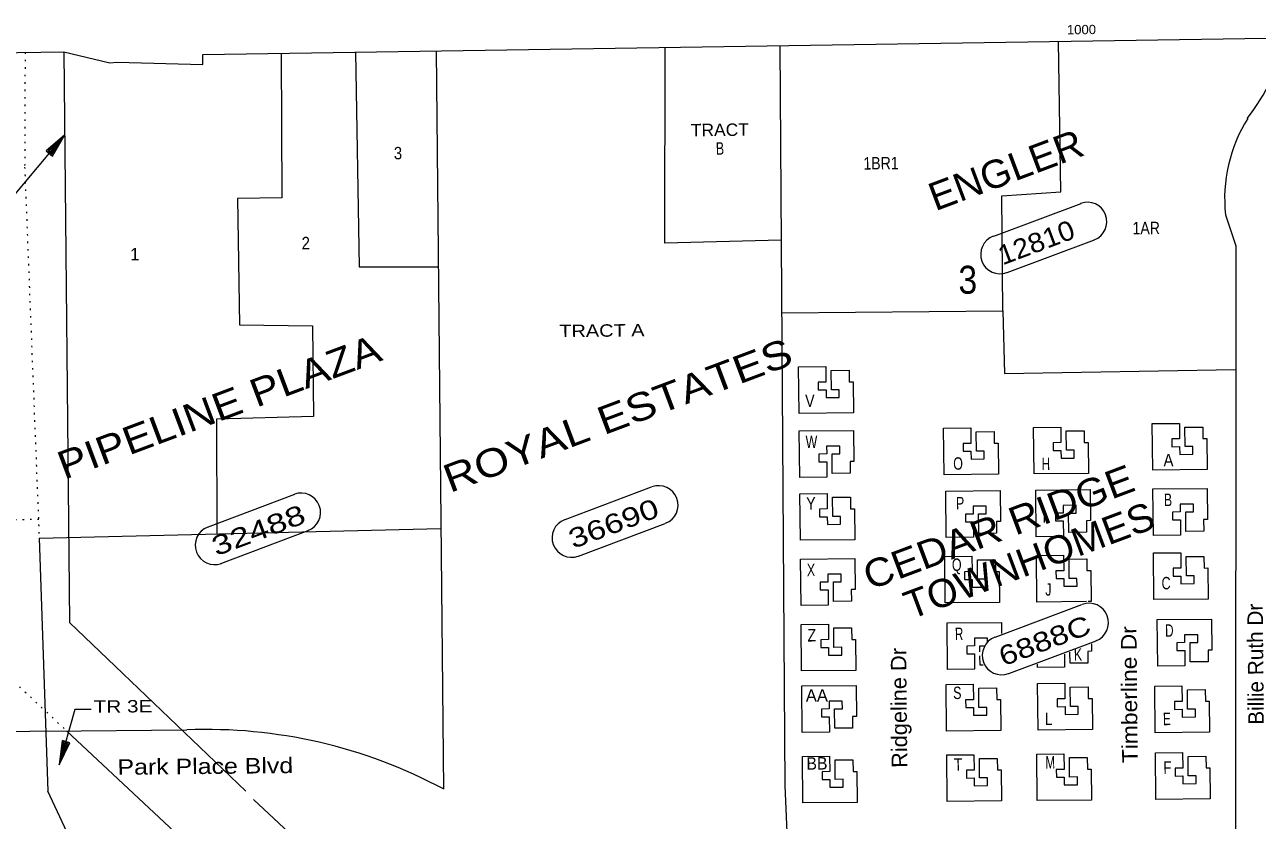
# Model space of a CAD drawing. Extents: x 2356373 to 2371954, y 6966197 to 6989612.
# Drawn here: x 2368672 to 2370261, y 6984875 to 6985900 of the extents above; entities that cross this region are included whole.
import ezdxf

# ---------------------------------------------------------------- set-up
doc = ezdxf.new("R2010")
doc.units = 0
doc.header["$LTSCALE"] = 6.4
doc.linetypes.add('DOTTED', pattern=[1.5, 0.3, -1.2])
for name, color, linetype in [('10', 7, 'Continuous'), ('18', 7, 'Continuous'), ('22', 7, 'Continuous'), ('24', 7, 'Continuous')]:
    doc.layers.add(name, color=color, linetype=linetype)
for name, color, linetype, lineweight in [('12', 7, 'Continuous', 13), ('15', 7, 'Continuous', 13), ('16', 7, 'DOTTED', 13), ('17', 7, 'Continuous', 13), ('19', 7, 'Continuous', 13), ('5', 7, 'DOTTED', 13), ('6', 7, 'DOTTED', 13), ('9', 7, 'DOTTED', 13)]:
    doc.layers.add(name, color=color, linetype=linetype, lineweight=lineweight)

msp = doc.modelspace()

# ---------------------------------------------------------------- linework, layer by layer
at = {"layer": '15'}
for points in [[(2368495.277, 6985845.388), (2368514.109, 6985861.969), (2368723.026, 6985864.722), (2368782.15, 6985850.505), (2368791.137, 6985851.594), (2368902.135, 6985848.686), (2368902.012, 6985861.28), (2370300.429, 6985882.714)], [(2370219.69, 6985654.681), (2370233.078, 6985614.824), (2370232.809, 6984778.145)]]:
    msp.add_lwpolyline(points, dxfattribs=at)
for centre, radius, start, end in [((2369996.656, 6985969.506), 315.251, 322.79276, 344.01276), ((2370412.432, 6985675.67), 193.829, 147.82276, 186.21276)]:
    msp.add_arc(centre, radius, start, end, dxfattribs=at)
at = {"layer": '16', "linetype": 'Continuous'}
for p, q in [((2369645.702, 6985872.683), (2369652.062, 6984919.802)), ((2369202.886, 6985865.935), (2369212.225, 6984915.281)), ((2369932.979, 6985531.298), (2369931.526, 6985679.184)), ((2369648.081, 6985528.599), (2369932.979, 6985531.298)), ((2368691.188, 6985238.375), (2368702.328, 6984912.462)), ((2368699.629, 6984989.725), (2368881.563, 6984991.41)), ((2369652.062, 6984919.802), (2369658.507, 6984772.503))]:
    msp.add_line(p, q, dxfattribs=at)
at = {"layer": '16'}
msp.add_lwpolyline([(2368673.045, 6985864.131), (2368672.496, 6985716.363), (2368691.188, 6985238.375)], dxfattribs=at)
at = {"layer": '16', "linetype": 'Continuous'}
for points in [[(2369932.979, 6985531.298), (2369934.773, 6985450.436), (2370232.642, 6985455.761)], [(2369150.575, 6984270.447), (2368981.634, 6984269.187), (2368972.151, 6984623.8), (2368837.184, 6984624.074), (2368702.328, 6984912.462)]]:
    msp.add_lwpolyline(points, dxfattribs=at)
msp.add_arc((2368906.902, 6984345.633), 646.306, 61.81376, 92.24176, dxfattribs=at)
at = {"layer": '17'}
for p, q in [((2369921.038, 6985627.354), (2370033.593, 6985669.549)), ((2369938.493, 6985580.638), (2370051.049, 6985622.732)), ((2369368.772, 6985262.226), (2369480.33, 6985304.311)), ((2368907.989, 6985252.702), (2369020.546, 6985294.895)), ((2369386.229, 6985215.41), (2369497.785, 6985257.494)), ((2368925.444, 6985205.885), (2369038, 6985248.08)), ((2369923.113, 6985110.813), (2370034.668, 6985152.997)), ((2369940.566, 6985064.097), (2370053.124, 6985106.191))]:
    msp.add_line(p, q, dxfattribs=at)
for centre, start, end in [((2370041.821, 6985646.136), 290.56276, 110.56276), ((2369929.266, 6985603.942), 110.56276, 290.56276), ((2369489.557, 6985280.908), 290.56276, 110.56276), ((2369028.773, 6985271.483), 290.56276, 110.56276), ((2368917.217, 6985229.298), 110.56276, 290.56276), ((2369377.001, 6985238.813), 110.56276, 290.56276), ((2370043.896, 6985129.594), 290.56276, 110.56276), ((2369931.341, 6985087.4), 110.56276, 290.56276)]:
    msp.add_arc(centre, 24.992, start, end, dxfattribs=at)
at = {"layer": '5', "linetype": 'Continuous'}
for points in [[(2368654.516, 6985613.015), (2368653.919, 6985673.893), (2368724.075, 6985757.96), (2368700.284, 6985737.33), (2368708.347, 6985730.612), (2368724.075, 6985757.96)], [(2368758.338, 6985017.894), (2368737.344, 6985017.687), (2368717.051, 6984946.307), (2368730.766, 6984974.934), (2368720.741, 6984977.735), (2368717.051, 6984946.307)], [(2368726.8, 6984989.981), (2369143.397, 6984600.308), (2369150.575, 6984270.447)]]:
    msp.add_lwpolyline(points, dxfattribs=at)
for points in [[(2368718.143, 6985751.202), (2368702.282, 6985737.451), (2368707.324, 6985732.901)], [(2368713.207, 6985744.757), (2368704.281, 6985737.57), (2368707.302, 6985735.2)], [(2368718.967, 6984954.724), (2368728.777, 6984973.915), (2368721.759, 6984975.845)], [(2368721.887, 6984962.85), (2368726.786, 6984972.896), (2368722.778, 6984973.856)]]:
    msp.add_lwpolyline(points, close=True, dxfattribs=at)
at = {"layer": '6', "linetype": 'Continuous'}
msp.add_line((2368691.188, 6985238.375), (2369208.929, 6985250.789), dxfattribs=at)
for points in [[(2369931.526, 6985679.184), (2370007.454, 6985684.488), (2370004.55, 6985878.208)], [(2369002.97, 6985862.872), (2369003.796, 6985676.829), (2368946.823, 6985675.769), (2368949.418, 6985513.239), (2369043.405, 6985512.063), (2369044.555, 6985395.105), (2368919.619, 6985391.878), (2368919.963, 6985243.861)], [(2369098.929, 6985864.313), (2369103.643, 6985587.934), (2369205.616, 6985588.036)], [(2369647.161, 6985622.365), (2369497.238, 6985618.493), (2369497.763, 6985870.43)], [(2370040.63, 6985156.755), (2369976.654, 6985156.126), (2369976.065, 6985216.106), (2370011.051, 6985216.448), (2370011.248, 6985196.456), (2370001.251, 6985196.357), (2370001.35, 6985186.361), (2370011.346, 6985186.46), (2370011.445, 6985176.463), (2370028.438, 6985176.63), (2370028.34, 6985186.625), (2370018.344, 6985186.528), (2370018.097, 6985211.52), (2370041.09, 6985211.746), (2370041.237, 6985196.75), (2370046.235, 6985196.799), (2370046.627, 6985156.815), (2370042.629, 6985156.774)], [(2369913.175, 6985104.817), (2369913.127, 6985109.715), (2369896.132, 6985109.548), (2369896.231, 6985099.552), (2369886.234, 6985099.455), (2369886.333, 6985089.459), (2369896.329, 6985089.555), (2369896.524, 6985069.563), (2369861.538, 6985069.22), (2369860.949, 6985129.196), (2369930.923, 6985129.885), (2369931.064, 6985115.589)], [(2369903.302, 6985092.123), (2369903.228, 6985099.621), (2369909.226, 6985099.68)], [(2370047.164, 6985102.234), (2370047.258, 6985092.636), (2370042.26, 6985092.588), (2370042.408, 6985077.594), (2370019.417, 6985077.368), (2370019.273, 6985091.763)], [(2369907.472, 6985074.669), (2369903.474, 6985074.629), (2369903.354, 6985086.825)], [(2370012.303, 6985089.095), (2370012.467, 6985072.3), (2369977.479, 6985071.957), (2369977.439, 6985076.056)]]:
    msp.add_lwpolyline(points, dxfattribs=at)
for points in [[(2369669.76, 6985459.031), (2369704.747, 6985459.374), (2369704.943, 6985439.381), (2369694.947, 6985439.284), (2369695.045, 6985429.286), (2369705.041, 6985429.385), (2369705.139, 6985419.388), (2369722.133, 6985419.556), (2369722.034, 6985429.552), (2369712.038, 6985429.453), (2369711.792, 6985454.444), (2369734.785, 6985454.671), (2369734.933, 6985439.677), (2369739.93, 6985439.725), (2369740.324, 6985399.74), (2369670.348, 6985399.051)], [(2369856.486, 6985379.986), (2369891.472, 6985380.33), (2369891.67, 6985360.337), (2369881.673, 6985360.239), (2369881.772, 6985350.243), (2369891.768, 6985350.34), (2369891.867, 6985340.345), (2369908.86, 6985340.512), (2369908.761, 6985350.508), (2369898.765, 6985350.41), (2369898.52, 6985375.401), (2369921.511, 6985375.627), (2369921.659, 6985360.632), (2369926.657, 6985360.681), (2369927.05, 6985320.696), (2369857.075, 6985320.008)], [(2369972.444, 6985381.125), (2370007.43, 6985381.468), (2370007.627, 6985361.476), (2369997.632, 6985361.377), (2369997.73, 6985351.382), (2370007.726, 6985351.48), (2370007.823, 6985341.483), (2370024.818, 6985341.65), (2370024.72, 6985351.647), (2370014.722, 6985351.549), (2370014.476, 6985376.539), (2370037.469, 6985376.766), (2370037.617, 6985361.771), (2370042.614, 6985361.821), (2370043.007, 6985321.836), (2369973.034, 6985321.147)], [(2370125.355, 6985385.926), (2370160.344, 6985386.27), (2370160.539, 6985366.278), (2370150.543, 6985366.178), (2370150.641, 6985356.183), (2370160.638, 6985356.28), (2370160.736, 6985346.283), (2370177.728, 6985346.452), (2370177.631, 6985356.448), (2370167.635, 6985356.349), (2370167.39, 6985381.341), (2370190.381, 6985381.566), (2370190.528, 6985366.572), (2370195.528, 6985366.622), (2370195.92, 6985326.636), (2370125.945, 6985325.948)], [(2369670.57, 6985376.462), (2369740.545, 6985377.148), (2369740.938, 6985337.162), (2369735.938, 6985337.114), (2369736.087, 6985322.119), (2369713.094, 6985321.893), (2369712.85, 6985346.883), (2369722.846, 6985346.982), (2369722.748, 6985356.979), (2369705.754, 6985356.812), (2369705.852, 6985346.815), (2369695.857, 6985346.716), (2369695.953, 6985336.721), (2369705.95, 6985336.818), (2369706.146, 6985316.826), (2369671.159, 6985316.483)], [(2369975.237, 6985300.274), (2370045.213, 6985300.962), (2370045.605, 6985260.976), (2370040.607, 6985260.927), (2370040.753, 6985245.932), (2370017.762, 6985245.707), (2370017.517, 6985270.698), (2370027.512, 6985270.795), (2370027.414, 6985280.793), (2370010.421, 6985280.625), (2370010.52, 6985270.63), (2370000.524, 6985270.53), (2370000.621, 6985260.535), (2370010.617, 6985260.633), (2370010.814, 6985240.639), (2369975.826, 6985240.295)], [(2370126.183, 6985301.756), (2370196.157, 6985302.445), (2370196.549, 6985262.458), (2370191.552, 6985262.409), (2370191.698, 6985247.417), (2370168.708, 6985247.189), (2370168.461, 6985272.179), (2370178.457, 6985272.279), (2370178.36, 6985282.275), (2370161.367, 6985282.108), (2370161.465, 6985272.112), (2370151.467, 6985272.013), (2370151.566, 6985262.017), (2370161.563, 6985262.114), (2370161.759, 6985242.122), (2370126.772, 6985241.779)], [(2369671.363, 6985295.69), (2369706.352, 6985296.033), (2369706.547, 6985276.041), (2369696.551, 6985275.942), (2369696.649, 6985265.947), (2369706.646, 6985266.045), (2369706.743, 6985256.048), (2369723.738, 6985256.215), (2369723.64, 6985266.211), (2369713.642, 6985266.114), (2369713.398, 6985291.104), (2369736.389, 6985291.331), (2369736.536, 6985276.334), (2369741.534, 6985276.384), (2369741.928, 6985236.4), (2369671.953, 6985235.712)], [(2369859.279, 6985299.135), (2369929.254, 6985299.823), (2369929.648, 6985259.837), (2369924.648, 6985259.787), (2369924.796, 6985244.794), (2369901.804, 6985244.567), (2369901.559, 6985269.559), (2369911.555, 6985269.657), (2369911.458, 6985279.653), (2369894.463, 6985279.486), (2369894.561, 6985269.49), (2369884.566, 6985269.392), (2369884.664, 6985259.396), (2369894.659, 6985259.493), (2369894.856, 6985239.501), (2369859.868, 6985239.157)], [(2369672.191, 6985211.521), (2369742.164, 6985212.209), (2369742.558, 6985172.223), (2369737.56, 6985172.172), (2369737.708, 6985157.18), (2369714.716, 6985156.952), (2369714.469, 6985181.945), (2369724.466, 6985182.043), (2369724.368, 6985192.04), (2369707.374, 6985191.872), (2369707.472, 6985181.875), (2369697.476, 6985181.777), (2369697.573, 6985171.781), (2369707.569, 6985171.879), (2369707.767, 6985151.887), (2369672.78, 6985151.542)], [(2369858.107, 6985214.946), (2369893.094, 6985215.289), (2369893.291, 6985195.298), (2369883.295, 6985195.198), (2369883.393, 6985185.202), (2369893.389, 6985185.301), (2369893.487, 6985175.304), (2369910.481, 6985175.471), (2369910.382, 6985185.468), (2369900.386, 6985185.369), (2369900.141, 6985210.361), (2369923.132, 6985210.587), (2369923.279, 6985195.591), (2369928.277, 6985195.641), (2369928.67, 6985155.656), (2369858.695, 6985154.968)], [(2370126.992, 6985219.287), (2370161.98, 6985219.632), (2370162.177, 6985199.639), (2370152.18, 6985199.54), (2370152.278, 6985189.543), (2370162.275, 6985189.641), (2370162.373, 6985179.644), (2370179.366, 6985179.811), (2370179.269, 6985189.809), (2370169.271, 6985189.711), (2370169.027, 6985214.701), (2370192.018, 6985214.928), (2370192.165, 6985199.933), (2370197.163, 6985199.98), (2370197.557, 6985159.996), (2370127.582, 6985159.309)], [(2369673.017, 6985127.351), (2369708.005, 6985127.695), (2369708.201, 6985107.701), (2369698.204, 6985107.603), (2369698.302, 6985097.608), (2369708.299, 6985097.705), (2369708.397, 6985087.709), (2369725.391, 6985087.877), (2369725.293, 6985097.873), (2369715.295, 6985097.774), (2369715.051, 6985122.766), (2369738.042, 6985122.992), (2369738.19, 6985107.997), (2369743.188, 6985108.045), (2369743.58, 6985068.06), (2369673.606, 6985067.373)], [(2370131.834, 6985133.458), (2370201.809, 6985134.144), (2370202.202, 6985094.159), (2370197.203, 6985094.11), (2370197.35, 6985079.116), (2370174.358, 6985078.889), (2370174.114, 6985103.881), (2370184.11, 6985103.979), (2370184.011, 6985113.975), (2370167.018, 6985113.808), (2370167.116, 6985103.811), (2370157.12, 6985103.714), (2370157.219, 6985093.717), (2370167.215, 6985093.815), (2370167.411, 6985073.822), (2370132.424, 6985073.479)], [(2369673.796, 6985048.079), (2369743.769, 6985048.768), (2369744.163, 6985008.782), (2369739.165, 6985008.732), (2369739.312, 6984993.739), (2369716.32, 6984993.511), (2369716.075, 6985018.503), (2369726.071, 6985018.601), (2369725.973, 6985028.599), (2369708.979, 6985028.431), (2369709.078, 6985018.435), (2369699.08, 6985018.337), (2369699.179, 6985008.34), (2369709.176, 6985008.438), (2369709.372, 6984988.445), (2369674.385, 6984988.102)], [(2369859.728, 6985049.907), (2369894.716, 6985050.25), (2369894.911, 6985030.257), (2369884.916, 6985030.159), (2369885.014, 6985020.162), (2369895.01, 6985020.26), (2369895.109, 6985010.265), (2369912.103, 6985010.43), (2369912.005, 6985020.428), (2369902.008, 6985020.33), (2369901.762, 6985045.32), (2369924.753, 6985045.547), (2369924.9, 6985030.552), (2369929.899, 6985030.601), (2369930.291, 6984990.615), (2369860.317, 6984989.928)], [(2369977.686, 6985051.064), (2370012.672, 6985051.408), (2370012.869, 6985031.416), (2370002.873, 6985031.318), (2370002.97, 6985021.321), (2370012.967, 6985021.419), (2370013.066, 6985011.424), (2370030.059, 6985011.59), (2370029.961, 6985021.587), (2370019.965, 6985021.488), (2370019.719, 6985046.479), (2370042.711, 6985046.704), (2370042.858, 6985031.71), (2370047.855, 6985031.76), (2370048.248, 6984991.774), (2369978.275, 6984991.087)], [(2370128.678, 6985047.649), (2370163.665, 6985047.992), (2370163.863, 6985028), (2370153.866, 6985027.902), (2370153.964, 6985017.906), (2370163.96, 6985018.004), (2370164.058, 6985008.007), (2370181.053, 6985008.175), (2370180.955, 6985018.171), (2370170.957, 6985018.072), (2370170.712, 6985043.063), (2370193.703, 6985043.288), (2370193.851, 6985028.296), (2370198.849, 6985028.344), (2370199.242, 6984988.358), (2370129.268, 6984987.672)], [(2369674.687, 6984957.312), (2369709.674, 6984957.657), (2369709.872, 6984937.664), (2369699.875, 6984937.566), (2369699.973, 6984927.57), (2369709.969, 6984927.668), (2369710.067, 6984917.671), (2369727.062, 6984917.839), (2369726.962, 6984927.834), (2369716.966, 6984927.735), (2369716.721, 6984952.727), (2369739.712, 6984952.953), (2369739.86, 6984937.959), (2369744.858, 6984938.008), (2369745.251, 6984898.022), (2369675.276, 6984897.334)], [(2369860.619, 6984959.14), (2369895.607, 6984959.483), (2369895.804, 6984939.49), (2369885.808, 6984939.392), (2369885.905, 6984929.395), (2369895.902, 6984929.494), (2369896, 6984919.497), (2369912.994, 6984919.663), (2369912.896, 6984929.66), (2369902.899, 6984929.562), (2369902.652, 6984954.554), (2369925.645, 6984954.779), (2369925.792, 6984939.785), (2369930.791, 6984939.833), (2369931.183, 6984899.849), (2369861.208, 6984899.16)], [(2369976.577, 6984960.278), (2370011.564, 6984960.621), (2370011.761, 6984940.629), (2370001.764, 6984940.531), (2370001.863, 6984930.535), (2370011.859, 6984930.633), (2370011.958, 6984920.635), (2370028.951, 6984920.804), (2370028.852, 6984930.799), (2370018.857, 6984930.701), (2370018.611, 6984955.693), (2370041.602, 6984955.917), (2370041.75, 6984940.924), (2370046.749, 6984940.972), (2370047.14, 6984900.988), (2369977.167, 6984900.3)], [(2370129.522, 6984961.781), (2370164.509, 6984962.124), (2370164.706, 6984942.131), (2370154.709, 6984942.033), (2370154.808, 6984932.036), (2370164.803, 6984932.136), (2370164.902, 6984922.139), (2370181.897, 6984922.306), (2370181.798, 6984932.302), (2370171.801, 6984932.204), (2370171.555, 6984957.195), (2370194.548, 6984957.422), (2370194.695, 6984942.426), (2370199.693, 6984942.475), (2370200.085, 6984902.49), (2370130.111, 6984901.801)]]:
    msp.add_lwpolyline(points, close=True, dxfattribs=at)
at = {"layer": '9', "linetype": 'Continuous'}
for p, q in [((2368723.027, 6985864.62), (2368730.243, 6985129.887)), ((2368957.318, 6984912.577), (2368730.243, 6985129.887)), ((2368699.629, 6984989.725), (2368506.977, 6984985.982))]:
    msp.add_line(p, q, dxfattribs=at)
at = {"layer": '9'}
for p, q in [((2368690.953, 6985262.367), (2368500.072, 6985260.491)), ((2368630.762, 6985079.803), (2368726.8, 6984989.981))]:
    msp.add_line(p, q, dxfattribs=at)
at = {"layer": '9', "linetype": 'Continuous'}
msp.add_lwpolyline([(2368967.421, 6984901.779), (2369234.807, 6984651.672), (2369240.537, 6984271.931)], dxfattribs=at)

# ---------------------------------------------------------------- texts
at = {"layer": '10', "width": 1.25}
msp.add_text('TR 3E', height=15.99, rotation=0.563, dxfattribs=at).set_placement((2368761.38, 6985013.425))
at = {"layer": '12'}
for s, width, p in [('TRACT', 1.05, (2369530.879, 6985755.987)), ('B', 0.75, (2369563.103, 6985732.309)), ('3', 0.9, (2369148.272, 6985726.336)), ('1BR1', 0.85, (2369753.239, 6985713.183)), ('1AR', 0.85, (2370099.968, 6985629.712)), ('2', 0.9, (2369029.442, 6985610.499)), ('TRACT A', 1.2, (2369361.466, 6985497.292)), ('V', 0.85, (2369678.266, 6985407.229)), ('W', 0.75, (2369678.783, 6985354.447)), ('O', 0.75, (2369869.008, 6985326.524)), ('H', 0.7, (2369982.983, 6985326.044)), ('A', 0.9, (2370139.893, 6985330.885)), ('Y', 0.85, (2369679.562, 6985275.175)), ('P', 0.75, (2369872.509, 6985275.471)), ('B', 0.75, (2370140.396, 6985279.702)), ('I', 0.9, (2369983.647, 6985258.367)), ('X', 0.75, (2369680.405, 6985189.408)), ('Q', 0.75, (2369867.29, 6985196.141)), ('C', 0.75, (2370137.451, 6985172.401)), ('J', 0.75, (2369987.57, 6985164.332)), ('D', 0.7, (2370142.049, 6985111.363)), ('Z', 0.85, (2369681.232, 6985105.237)), ('R', 0.7, (2369871.163, 6985107.103)), ('K', 0.75, (2370024.383, 6985080.516)), ('S', 0.75, (2369868.91, 6985031.101)), ('L', 0.8, (2369987.208, 6984997.672)), ('E', 0.7, (2370139.168, 6984997.467)), ('BB', 0.95, (2369679.855, 6984940.168)), ('T', 0.85, (2369869.818, 6984938.734)), ('M', 0.7, (2369987.759, 6984941.593)), ('F', 0.8, (2370139.784, 6984934.788))]:
    msp.add_text(s, height=15.99, rotation=0.563, dxfattribs=dict(at, width=width)).set_placement(p)
for s, p in [('1', (2368808.642, 6985596.135)), ('AA', (2369678.995, 6985027.637))]:
    msp.add_text(s, height=15.99, rotation=0.563, dxfattribs=at).set_placement(p)
at = {"layer": '17'}
for s, width, p in [('12810', 1.1, (2369932.405, 6985589.676)), ('36690', 1.3, (2369379.142, 6985224.438)), ('32488', 1.35, (2368919.357, 6985214.923)), ('6888C', 1.25, (2369933.48, 6985073.124))]:
    msp.add_text(s, height=24.99, rotation=20.563, dxfattribs=dict(at, width=width)).set_placement(p)
at = {"layer": '18'}
for s, width, p in [('ENGLER', 1.05, (2369845.745, 6985659.306)), ('PIPELINE PLAZA', 1.15, (2368723.442, 6985313.471)), ('ROYAL ESTATES', 1.2, (2369220.476, 6985296.46)), ('CEDAR RIDGE', 1.1, (2369761.563, 6985171.209)), ('TOWNHOMES', 1.05, (2369813.921, 6985133.234))]:
    msp.add_text(s, height=35.99, rotation=20.563, dxfattribs=dict(at, width=width)).set_placement(p)
at = {"layer": '19'}
msp.add_text('Billie Ruth Dr', height=19.98, rotation=90.5, dxfattribs=at).set_placement((2370269.127, 6984998.142))
for s, rotation, width, p in [('Timberline Dr', 90.563, 1.1, (2370106.658, 6984948.659)), ('Ridgeline Dr', 90.563, 1.05, (2369809.796, 6984942.545)), ('Park Place Blvd', 0.563, 1.2, (2368792.157, 6984933.548))]:
    msp.add_text(s, height=19.99, rotation=rotation, dxfattribs=dict(at, width=width)).set_placement(p)
at = {"layer": '22', "width": 0.9}
msp.add_text('3', height=35.99, rotation=0.563, dxfattribs=at).set_placement((2369875.781, 6985553.13))
at = {"layer": '24', "width": 1.05}
msp.add_text('1000', height=12, rotation=0.563, dxfattribs=at).set_placement((2370015.459, 6985887.313))

doc.saveas('drawing.dxf')
